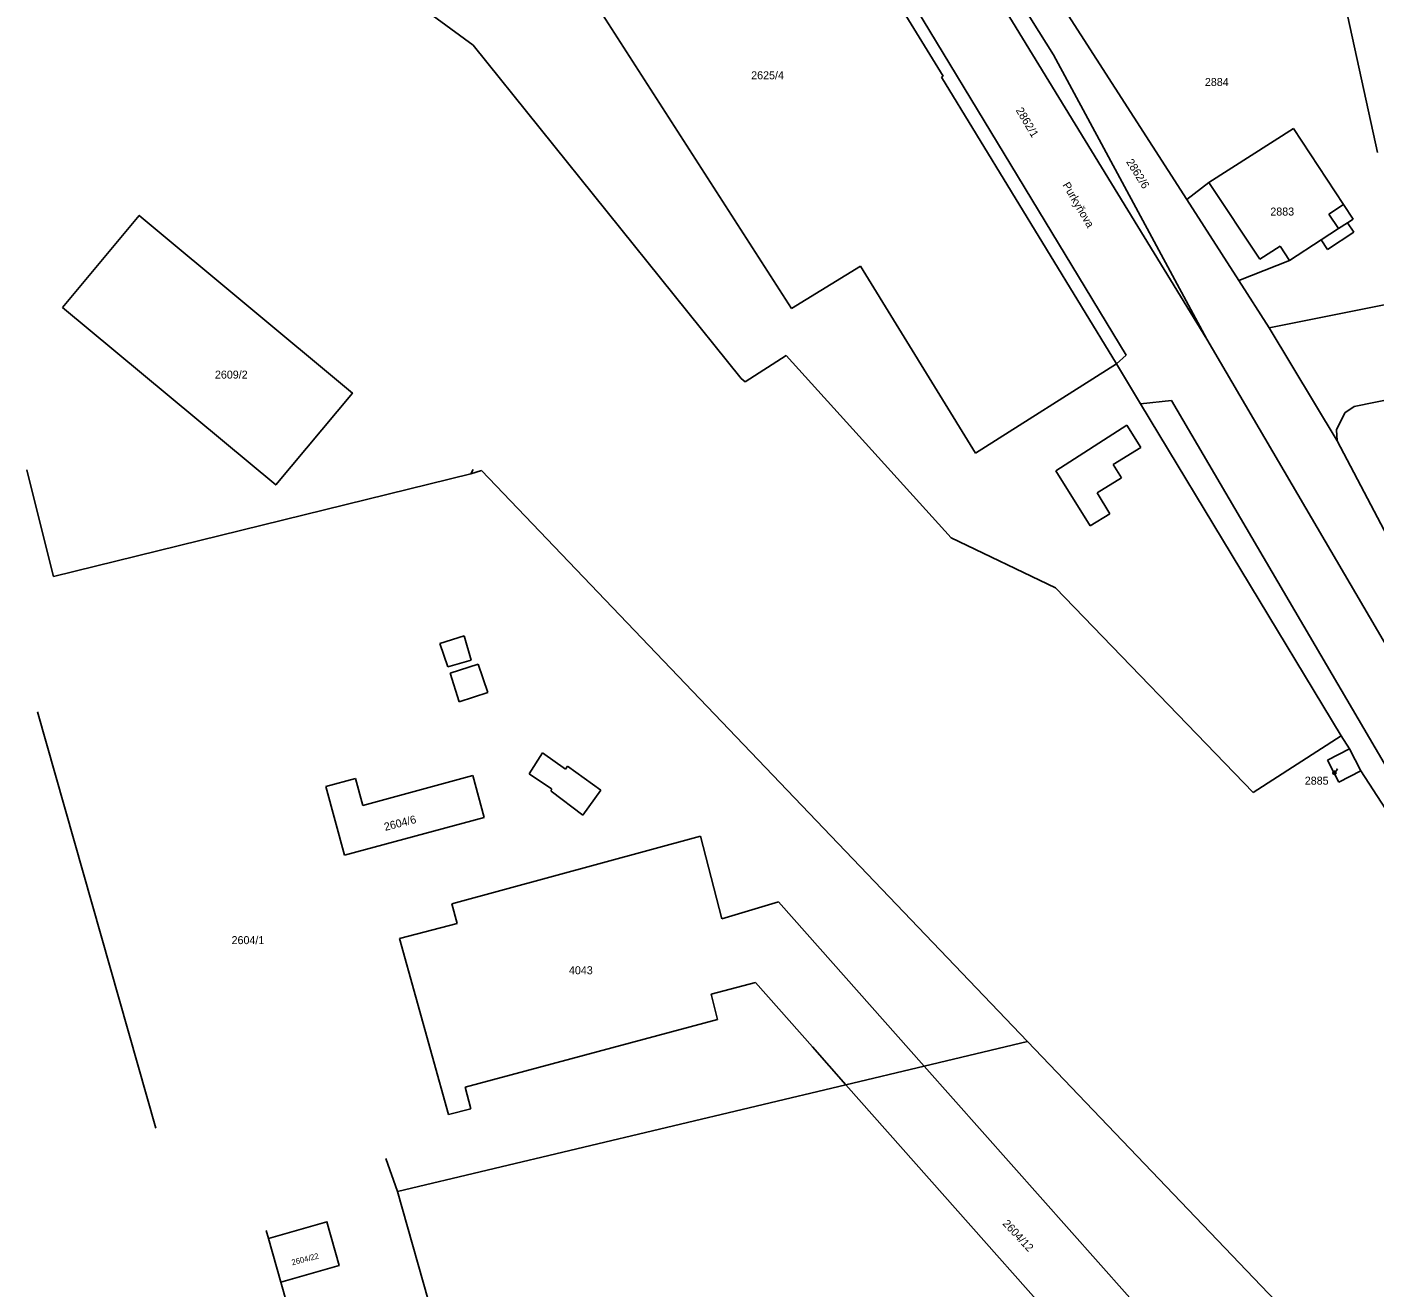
# Model space of a CAD drawing. Extents: x -722132 to -721608, y -1046877 to -1046449.
# Drawn here: x -722132.1 to -721988.9, y -1046720.6 to -1046586.7 of the extents above; entities that cross this region are included whole.
import ezdxf

# ---------------------------------------------------------------- set-up
doc = ezdxf.new("R2010")
doc.units = 0
for name, color, linetype in [('Vrstva 1', 7, 'Continuous'), ('Vrstva 15', 7, 'Continuous'), ('Vrstva 16', 7, 'Continuous'), ('Vrstva 18', 7, 'Continuous'), ('Vrstva 19', 7, 'Continuous'), ('Vrstva 4', 7, 'Continuous'), ('Vrstva 6', 7, 'Continuous')]:
    doc.layers.add(name, color=color, linetype=linetype)

msp = doc.modelspace()

# ---------------------------------------------------------------- linework, layer by layer
at = {"layer": 'Vrstva 1'}
msp.add_line((-722092.7, -1046710.44), (-722082, -1046748.2), dxfattribs=at)
for points in [[(-722046.17, -1046573.26), (-722034.73, -1046591.91)], [(-721993.21, -1046578.75), (-721988.59, -1046600.03)], [(-722074.42, -1046579.87), (-722050.83, -1046616.6)], [(-722089.92, -1046584.74), (-722084.64, -1046588.61)], [(-722022.07, -1046584.43), (-722008.84, -1046605.03)], [(-722084.64, -1046588.61), (-722056.16, -1046624.05)], [(-722034.9, -1046592.02), (-722034.73, -1046591.91)], [(-722034.9, -1046592.02), (-722016.31, -1046622.48)], [(-722006.48, -1046603.22), (-721997.51, -1046597.48)], [(-721997.51, -1046597.48), (-721992.2, -1046605.55)], [(-722008.84, -1046605.03), (-722006.48, -1046603.22)], [(-722008.84, -1046605.03), (-722003.31, -1046613.63)], [(-721992.2, -1046605.55), (-721991.17, -1046607.11)], [(-722128.26, -1046616.48), (-722120.12, -1046606.71), (-722097.48, -1046625.59), (-722105.61, -1046635.35), (-722128.26, -1046616.48)], [(-721991.75, -1046607.49), (-721991.17, -1046607.11)], [(-721991.75, -1046607.49), (-721991.1, -1046608.5)], [(-721993.9, -1046610.32), (-721991.1, -1046608.5)], [(-721997.93, -1046611.5), (-721994.56, -1046609.31)], [(-721994.56, -1046609.31), (-721993.9, -1046610.32)], [(-722003.31, -1046613.63), (-721997.93, -1046611.5)], [(-722050.83, -1046616.6), (-722043.48, -1046612.09)], [(-722043.48, -1046612.09), (-722031.29, -1046631.98)], [(-722003.31, -1046613.63), (-722000.08, -1046618.64)], [(-722000.08, -1046618.64), (-721985.2, -1046615.68)], [(-722000.08, -1046618.64), (-721992.85, -1046630.66)], [(-721991.07, -1046627.03), (-721951.12, -1046618.9)], [(-722006.7, -1046619.85), (-721980.36, -1046664.85)], [(-722055.76, -1046624.39), (-722051.41, -1046621.59)], [(-722051.41, -1046621.59), (-722033.86, -1046640.98)], [(-722031.29, -1046631.98), (-722016.31, -1046622.48)], [(-722016.31, -1046622.48), (-722013.75, -1046626.73)], [(-722056.16, -1046624.05), (-722055.76, -1046624.39)], [(-722013.75, -1046626.73), (-721992.45, -1046662.02)], [(-721992.94, -1046629.49), (-721992.05, -1046627.67)], [(-721992.05, -1046627.67), (-721991.07, -1046627.03)], [(-721992.94, -1046629.49), (-721992.85, -1046630.66)], [(-721992.85, -1046630.66), (-721981.77, -1046651.73)], [(-722129.22, -1046645.09), (-722084.91, -1046634.18)], [(-722084.91, -1046634.18), (-722084.66, -1046633.71)], [(-722084.91, -1046634.18), (-722083.75, -1046633.83)], [(-722083.75, -1046633.83), (-722025.76, -1046694.5)], [(-722033.86, -1046640.98), (-722022.79, -1046646.29)], [(-722022.79, -1046646.29), (-722001.79, -1046668.03)], [(-722130.92, -1046659.48), (-722118.36, -1046703.71)], [(-722001.79, -1046668.03), (-721992.45, -1046662.02)], [(-721992.45, -1046662.02), (-721991.54, -1046663.41)], [(-721993.87, -1046664.61), (-721991.54, -1046663.41)], [(-721991.54, -1046663.41), (-721990.34, -1046665.74)], [(-721993.87, -1046664.61), (-721992.68, -1046666.94)], [(-722096.35, -1046669.41), (-722084.69, -1046666.24)], [(-722084.69, -1046666.24), (-722083.48, -1046670.68)], [(-721992.68, -1046666.94), (-721991.51, -1046666.34)], [(-721991.51, -1046666.34), (-721990.34, -1046665.74)], [(-722100.3, -1046667.4), (-722097.13, -1046666.55)], [(-722100.3, -1046667.4), (-722098.32, -1046674.69)], [(-722097.13, -1046666.55), (-722096.35, -1046669.41)], [(-722098.32, -1046674.69), (-722083.48, -1046670.68)], [(-722086.9, -1046679.86), (-722060.49, -1046672.67)], [(-722060.49, -1046672.67), (-722058.22, -1046681.45)], [(-722086.9, -1046679.86), (-722086.35, -1046681.96)], [(-722058.22, -1046681.45), (-722052.21, -1046679.67)], [(-722052.21, -1046679.67), (-722036.73, -1046697.11)], [(-722092.47, -1046683.56), (-722086.35, -1046681.96)], [(-722092.47, -1046683.56), (-722087.27, -1046702.25)], [(-722059.36, -1046689.47), (-722054.65, -1046688.23)], [(-722054.65, -1046688.23), (-722048.61, -1046695.06)], [(-722059.36, -1046689.47), (-722058.68, -1046692.17)], [(-722085.49, -1046699.36), (-722058.68, -1046692.17)], [(-722048.61, -1046695.06), (-722045.04, -1046699.09)], [(-722036.73, -1046697.11), (-722025.76, -1046694.5)], [(-722025.76, -1046694.5), (-721989.29, -1046732.65)], [(-722045.04, -1046699.09), (-722036.73, -1046697.11)], [(-722036.73, -1046697.11), (-722002.84, -1046735.3)], [(-722092.7, -1046710.44), (-722045.04, -1046699.09)], [(-722085.49, -1046699.36), (-722084.88, -1046701.64)], [(-722045.04, -1046699.09), (-722011.04, -1046737.52)], [(-722087.27, -1046702.25), (-722084.88, -1046701.64)], [(-722093.94, -1046706.92), (-722092.7, -1046710.44)], [(-722106.38, -1046715.42), (-722100.19, -1046713.66), (-722098.89, -1046718.31), (-722105.07, -1046720.06)], [(-722106.62, -1046714.58), (-722106.38, -1046715.42)], [(-722106.38, -1046715.42), (-722105.07, -1046720.06)], [(-722105.07, -1046720.06), (-722098.23, -1046744.19)]]:
    msp.add_lwpolyline(points, dxfattribs=at)
at = {"layer": 'Vrstva 16'}
msp.add_lwpolyline([(-721992.84, -1046665.55), (-721993.15, -1046665.94)], dxfattribs=at)
msp.add_circle((-721993.15, -1046665.94), 0.175, dxfattribs=at)
at = {"layer": 'Vrstva 4'}
for points in [[(-722045.87, -1046555.83), (-722006.7, -1046619.85)], [(-722050.51, -1046563.35), (-722015.29, -1046621.57)], [(-722006.48, -1046603.22), (-722001.07, -1046611.37)], [(-721993.74, -1046606.56), (-721992.2, -1046605.55)], [(-721993.74, -1046606.56), (-721992.72, -1046608.11)], [(-721992.72, -1046608.11), (-721991.75, -1046607.49)], [(-721994.56, -1046609.31), (-721992.72, -1046608.11)], [(-722001.07, -1046611.37), (-721998.92, -1046609.97)], [(-721998.92, -1046609.97), (-721997.93, -1046611.5)], [(-722016.31, -1046622.48), (-722015.29, -1046621.57)], [(-722013.75, -1046626.73), (-722010.47, -1046626.38)], [(-722010.47, -1046626.38), (-721970.8, -1046694.03)], [(-722022.75, -1046633.85), (-722015.21, -1046628.99)], [(-722015.21, -1046628.99), (-722013.72, -1046631.36)], [(-722016.66, -1046633.19), (-722013.72, -1046631.36)], [(-722016.66, -1046633.19), (-722015.78, -1046634.6)], [(-722132.05, -1046633.73), (-722129.75, -1046642.98)], [(-722022.75, -1046633.85), (-722019.09, -1046639.71)], [(-722018.37, -1046636.2), (-722015.78, -1046634.6)], [(-722018.37, -1046636.2), (-722017, -1046638.41)], [(-722019.09, -1046639.71), (-722017, -1046638.41)], [(-722129.75, -1046642.98), (-722129.22, -1046645.09)], [(-722088.17, -1046652.2), (-722085.61, -1046651.38)], [(-722085.61, -1046651.38), (-722084.87, -1046653.98)], [(-722088.17, -1046652.2), (-722087.35, -1046654.68)], [(-722087.35, -1046654.68), (-722084.87, -1046653.98)], [(-722087.08, -1046655.37), (-722084.11, -1046654.41)], [(-722084.11, -1046654.41), (-722083.1, -1046657.41)], [(-722087.08, -1046655.37), (-722086.13, -1046658.4)], [(-722086.13, -1046658.4), (-722083.1, -1046657.41)], [(-722078.69, -1046666.04), (-722077.28, -1046663.83)], [(-722077.28, -1046663.83), (-722074.83, -1046665.56)], [(-722078.69, -1046666.04), (-722076.32, -1046667.65)], [(-722074.83, -1046665.56), (-722074.61, -1046665.24)], [(-722074.61, -1046665.24), (-722071.1, -1046667.8)], [(-722076.37, -1046667.91), (-722076.32, -1046667.65)], [(-722073.01, -1046670.45), (-722071.1, -1046667.8)], [(-722076.37, -1046667.91), (-722073.01, -1046670.45)]]:
    msp.add_lwpolyline(points, dxfattribs=at)
at = {"layer": 'Vrstva 6'}
for points in [[(-722062.93, -1046526), (-722023.01, -1046589.63)], [(-722023.01, -1046589.63), (-722006.7, -1046619.85)], [(-721990.34, -1046665.74), (-721982.96, -1046677.13)]]:
    msp.add_lwpolyline(points, dxfattribs=at)

# ---------------------------------------------------------------- texts
at = {"layer": 'Vrstva 15'}
msp.add_text('Purkyňova', height=0.85, rotation=300.3649, dxfattribs=at).set_placement((-722022.07, -1046603.47))
at = {"layer": 'Vrstva 16'}
msp.add_text('2885', height=0.85, dxfattribs=at).set_placement((-721996.3, -1046667.2))
at = {"layer": 'Vrstva 18'}
for s, p in [('2884', (-722006.91, -1046592.95)), ('2604/1', (-722110.31, -1046684.15)), ('4043', (-722074.47, -1046687.35))]:
    msp.add_text(s, height=0.85, dxfattribs=at).set_placement(p)
for s, rotation, p in [('2862/1', 300.6344, (-722027.03, -1046595.53)), ('2862/6', 301.9001, (-722015.31, -1046601.01)), ('2604/12', 313.0531, (-722028.46, -1046713.9))]:
    msp.add_text(s, height=0.85, rotation=rotation, dxfattribs=at).set_placement(p)
at = {"layer": 'Vrstva 19'}
for s, height, p in [('2625/4', 0.85, (-722055.11, -1046592.24)), ('2883', 0.85, (-721999.96, -1046606.72)), ('2609/2', 0.85, (-722112.08, -1046624.05)), ('2885', 0.1, (-721992.99, -1046665.55))]:
    msp.add_text(s, height=height, dxfattribs=at).set_placement(p)
for s, height, rotation, p in [('2604/6', 0.85, 14.3756, (-722093.99, -1046672.12)), ('2604/22', 0.61, 14.4761, (-722103.85, -1046718.29))]:
    msp.add_text(s, height=height, rotation=rotation, dxfattribs=at).set_placement(p)

doc.saveas('drawing.dxf')
